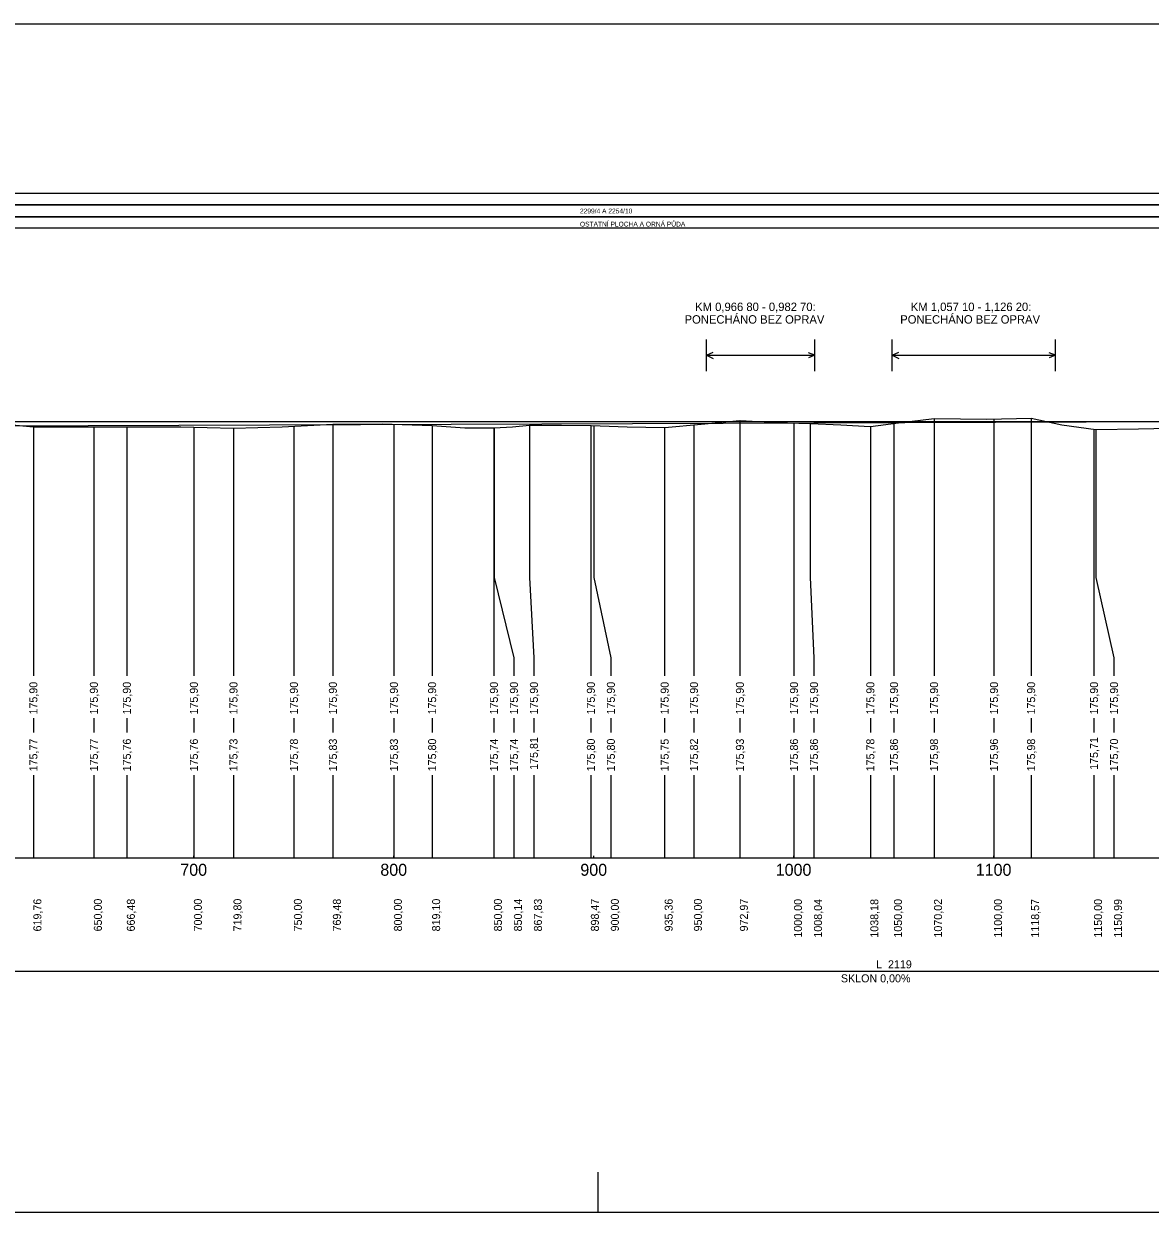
# Model space of a CAD drawing. Extents: x -614174 to -599765, y -1185887 to -1181080.
# Drawn here: x -612900 to -612336, y -1183382 to -1182788 of the extents above; entities that cross this region are included whole.
import ezdxf

# ---------------------------------------------------------------- set-up
doc = ezdxf.new("R2010")
doc.units = 0
for name, color, linetype in [('11', 7, 'Continuous'), ('13', 7, 'Continuous'), ('56', 7, 'Continuous'), ('návrh', 7, 'Continuous')]:
    doc.layers.add(name, color=color, linetype=linetype)

msp = doc.modelspace()

# ---------------------------------------------------------------- linework, layer by layer
msp.add_line((-613514.51, -1182987.26), (-611402.58, -1182987.26))
for points in [[(-612919.57, -1182987.61), (-612894.76, -1182989.95), (-612894.75, -1182989.95), (-612872.01, -1182989.86), (-612848.19, -1182989.96), (-612848.02, -1182989.96), (-612820.99, -1182989.96), (-612794.74, -1182990.58), (-612794.71, -1182990.58), (-612770.43, -1182989.89), (-612745.02, -1182988.57), (-612744.86, -1182988.56), (-612720.42, -1182988.46), (-612695.43, -1182989.26), (-612695.41, -1182989.26), (-612679.04, -1182990.36), (-612664.36, -1182990.36), (-612664.31, -1182990.36), (-612655.26, -1182989.95), (-612646.68, -1182989.08), (-612646.61, -1182989.07), (-612630.72, -1182988.97), (-612616.04, -1182989.26), (-612615.86, -1182989.26), (-612597.94, -1182989.85), (-612579.15, -1182990.26), (-612579.03, -1182990.26), (-612560.84, -1182988.5), (-612541.53, -1182986.67), (-612541.4, -1182986.66), (-612523.45, -1182987.78), (-612506.47, -1182988.15), (-612506.29, -1182988.16), (-612491.08, -1182988.8), (-612476.37, -1182989.64), (-612476.32, -1182989.64), (-612462.3, -1182987.86), (-612444.48, -1182985.65), (-612444.38, -1182985.64), (-612418.08, -1182986.06), (-612395.94, -1182985.57), (-612395.88, -1182985.56), (-612380.62, -1182988.96), (-612363.52, -1182991.27), (-612363.4, -1182991.29), (-612342.33, -1182990.94), (-612319.32, -1182990.34)], [(-612444.48, -1182985.65), (-612444.48, -1183065.26), (-612444.48, -1183105.26), (-612444.48, -1183114.34)], [(-612414.51, -1182985.98), (-612414.51, -1183065.26), (-612414.51, -1183105.26), (-612414.51, -1183114.34)], [(-612395.94, -1182985.57), (-612395.94, -1183065.26), (-612395.94, -1183105.26), (-612395.94, -1183114.34)], [(-612894.75, -1182989.95), (-612894.75, -1183065.26), (-612894.75, -1183105.26), (-612894.75, -1183114.34)], [(-612864.51, -1182989.89), (-612864.51, -1183065.26), (-612864.51, -1183105.26), (-612864.51, -1183114.34)], [(-612848.02, -1182989.96), (-612848.02, -1183065.26), (-612848.02, -1183105.26), (-612848.02, -1183114.34)], [(-612814.51, -1182990.11), (-612814.51, -1183065.26), (-612814.51, -1183105.26), (-612814.51, -1183114.34)], [(-612794.71, -1182990.58), (-612794.71, -1183065.26), (-612794.71, -1183105.26), (-612794.71, -1183114.34)], [(-612764.51, -1182989.58), (-612764.51, -1183065.26), (-612764.51, -1183105.26), (-612764.51, -1183114.34)], [(-612745.02, -1182988.57), (-612745.02, -1183065.26), (-612745.02, -1183105.26), (-612745.02, -1183114.34)], [(-612714.51, -1182988.65), (-612714.51, -1183065.26), (-612714.51, -1183105.26), (-612714.51, -1183114.34)], [(-612695.41, -1182989.26), (-612695.41, -1183065.26), (-612695.41, -1183105.26), (-612695.41, -1183114.34)], [(-612664.51, -1182990.36), (-612664.51, -1183065.26), (-612664.51, -1183105.26), (-612664.51, -1183114.34)], [(-612664.36, -1182990.36), (-612664.36, -1183065.26), (-612654.51, -1183105.26), (-612654.51, -1183114.34)], [(-612646.68, -1182989.08), (-612646.68, -1183065.26), (-612644.51, -1183105.26), (-612644.51, -1183114.34)], [(-612616.04, -1182989.26), (-612616.04, -1183065.26), (-612616.04, -1183105.26), (-612616.04, -1183114.34)], [(-612614.51, -1182989.3), (-612614.51, -1183065.26), (-612606.04, -1183105.26), (-612606.04, -1183114.34)], [(-612579.15, -1182990.26), (-612579.15, -1183065.26), (-612579.15, -1183105.26), (-612579.15, -1183114.34)], [(-612564.51, -1182988.86), (-612564.51, -1183065.26), (-612564.51, -1183105.26), (-612564.51, -1183114.34)], [(-612541.53, -1182986.67), (-612541.53, -1183065.26), (-612541.53, -1183105.26), (-612541.53, -1183114.34)], [(-612514.51, -1182987.97), (-612514.51, -1183065.26), (-612514.51, -1183105.26), (-612514.51, -1183114.34)], [(-612506.47, -1182988.15), (-612506.47, -1183065.26), (-612504.51, -1183105.26), (-612504.51, -1183114.34)], [(-612476.32, -1182989.64), (-612476.32, -1183065.26), (-612476.32, -1183105.26), (-612476.32, -1183114.34)], [(-612464.51, -1182988.13), (-612464.51, -1183065.26), (-612464.51, -1183105.26), (-612464.51, -1183114.34)], [(-612364.51, -1182991.14), (-612364.51, -1183065.26), (-612364.51, -1183105.26), (-612364.51, -1183114.34)], [(-612363.52, -1182991.27), (-612363.52, -1183065.26), (-612354.51, -1183105.26), (-612354.51, -1183114.34)], [(-612894.75, -1183135.54), (-612894.75, -1183142.7)], [(-612864.51, -1183135.54), (-612864.51, -1183142.7)], [(-612848.02, -1183135.54), (-612848.02, -1183142.7)], [(-612814.51, -1183135.54), (-612814.51, -1183142.7)], [(-612794.71, -1183135.54), (-612794.71, -1183142.7)], [(-612764.51, -1183135.54), (-612764.51, -1183142.7)], [(-612745.02, -1183135.54), (-612745.02, -1183142.7)], [(-612714.51, -1183135.54), (-612714.51, -1183142.7)], [(-612695.41, -1183135.54), (-612695.41, -1183142.7)], [(-612664.51, -1183135.54), (-612664.51, -1183142.7)], [(-612654.51, -1183135.54), (-612654.51, -1183142.7)], [(-612644.51, -1183135.54), (-612644.51, -1183142.7)], [(-612616.04, -1183135.54), (-612616.04, -1183142.7)], [(-612606.04, -1183135.54), (-612606.04, -1183142.7)], [(-612579.15, -1183135.54), (-612579.15, -1183142.7)], [(-612564.51, -1183135.54), (-612564.51, -1183142.7)], [(-612541.53, -1183135.54), (-612541.53, -1183142.7)], [(-612514.51, -1183135.54), (-612514.51, -1183142.7)], [(-612504.51, -1183135.54), (-612504.51, -1183142.7)], [(-612476.32, -1183135.54), (-612476.32, -1183142.7)], [(-612464.51, -1183135.54), (-612464.51, -1183142.7)], [(-612444.48, -1183135.54), (-612444.48, -1183142.7)], [(-612414.51, -1183135.54), (-612414.51, -1183142.7)], [(-612395.94, -1183135.54), (-612395.94, -1183142.7)], [(-612364.51, -1183135.54), (-612364.51, -1183142.7)], [(-612354.51, -1183135.54), (-612354.51, -1183142.7)], [(-612894.75, -1183163.91), (-612894.75, -1183205.26)], [(-612864.51, -1183163.91), (-612864.51, -1183205.26)], [(-612848.02, -1183163.91), (-612848.02, -1183205.26)], [(-612814.51, -1183163.91), (-612814.51, -1183205.26)], [(-612794.71, -1183163.91), (-612794.71, -1183205.26)], [(-612764.51, -1183163.91), (-612764.51, -1183205.26)], [(-612745.02, -1183163.91), (-612745.02, -1183205.26)], [(-612714.51, -1183163.91), (-612714.51, -1183205.26)], [(-612695.41, -1183163.91), (-612695.41, -1183205.26)], [(-612664.51, -1183163.91), (-612664.51, -1183205.26)], [(-612654.51, -1183163.91), (-612654.51, -1183205.26)], [(-612644.51, -1183163.91), (-612644.51, -1183205.26)], [(-612616.04, -1183163.91), (-612616.04, -1183205.26)], [(-612606.04, -1183163.91), (-612606.04, -1183205.26)], [(-612579.15, -1183163.91), (-612579.15, -1183205.26)], [(-612564.51, -1183163.91), (-612564.51, -1183205.26)], [(-612541.53, -1183163.91), (-612541.53, -1183205.26)], [(-612514.51, -1183163.91), (-612514.51, -1183205.26)], [(-612504.51, -1183163.91), (-612504.51, -1183205.26)], [(-612476.32, -1183163.91), (-612476.32, -1183205.26)], [(-612464.51, -1183163.91), (-612464.51, -1183205.26)], [(-612444.48, -1183163.91), (-612444.48, -1183205.26)], [(-612414.51, -1183163.91), (-612414.51, -1183205.26)], [(-612395.94, -1183163.91), (-612395.94, -1183205.26)], [(-612364.51, -1183163.91), (-612364.51, -1183205.26)], [(-612354.51, -1183163.91), (-612354.51, -1183205.26)], [(-613514.51, -1183261.99), (-611395.59, -1183261.99)]]:
    msp.add_lwpolyline(points)
at = {"layer": '56'}
for p, q in [((-613514.51, -1183205.26), (-611314.51, -1183205.26)), ((-612814.51, -1183205.26), (-612814.51, -1183204.26)), ((-612714.51, -1183205.26), (-612714.51, -1183204.26)), ((-612614.51, -1183205.26), (-612614.51, -1183204.26)), ((-612514.51, -1183205.26), (-612514.51, -1183204.26)), ((-612414.51, -1183205.26), (-612414.51, -1183204.26))]:
    msp.add_line(p, q, dxfattribs=at)
at = {"layer": 'návrh'}
for p, q in [((-613657.4, -1182788.43), (-610932.51, -1182788.43)), ((-612558.25, -1182961.98), (-612558.25, -1182946.2)), ((-612503.99, -1182961.98), (-612503.99, -1182946.2)), ((-612465.47, -1182961.98), (-612465.47, -1182946.2)), ((-612383.78, -1182961.98), (-612383.78, -1182946.2)), ((-612558.25, -1182954.09), (-612554.89, -1182952.64)), ((-612558.25, -1182954.09), (-612554.85, -1182955.65)), ((-612558.25, -1182954.09), (-612503.99, -1182954.09)), ((-612503.99, -1182954.09), (-612507.17, -1182952.85)), ((-612503.99, -1182954.09), (-612507.17, -1182955.45)), ((-612465.47, -1182954.09), (-612462.11, -1182952.64)), ((-612465.47, -1182954.09), (-612462.07, -1182955.65)), ((-612465.47, -1182954.09), (-612383.78, -1182954.09)), ((-612383.78, -1182954.09), (-612386.96, -1182952.85)), ((-612383.78, -1182954.09), (-612386.96, -1182955.45)), ((-611394.51, -1182984.06), (-613514.51, -1182991.66)), ((-612612.51, -1183362.43), (-612612.51, -1183382.43)), ((-613452.51, -1183382.43), (-610932.51, -1183382.43))]:
    msp.add_line(p, q, dxfattribs=at)
for points in [[(-613514.51, -1182873.17), (-611398.36, -1182873.17), (-611398.36, -1182879), (-613514.51, -1182879)], [(-613514.51, -1182879), (-611398.36, -1182879), (-611398.36, -1182884.84), (-613514.51, -1182884.84)], [(-613514.51, -1182884.84), (-611398.36, -1182884.84), (-611398.36, -1182890.67), (-613514.51, -1182890.67)]]:
    msp.add_lwpolyline(points, close=True, dxfattribs=at)

# ---------------------------------------------------------------- texts
at = {"layer": '11'}
for s, rotation, p in [('175,90', 90, (-612892.75, -1183133.67)), ('175,90', 90, (-612862.51, -1183133.67)), ('175,90', 90, (-612846.02, -1183133.67)), ('175,90', 90, (-612812.51, -1183133.67)), ('175,90', 90, (-612792.71, -1183133.67)), ('175,90', 90, (-612762.51, -1183133.67)), ('175,90', 90, (-612743.02, -1183133.67)), ('175,90', 90, (-612712.51, -1183133.67)), ('175,90', 90, (-612693.41, -1183133.67)), ('175,90', 90, (-612662.51, -1183133.67)), ('175,90', 90, (-612652.51, -1183133.67)), ('175,90', 90, (-612642.51, -1183133.67)), ('175,90', 90, (-612614.04, -1183133.67)), ('175,90', 90, (-612604.04, -1183133.67)), ('175,90', 90, (-612577.15, -1183133.67)), ('175,90', 90, (-612562.51, -1183133.67)), ('175,90', 90, (-612539.53, -1183133.67)), ('175,90', 90, (-612512.51, -1183133.67)), ('175,90', 90, (-612502.51, -1183133.67)), ('175,90', 90, (-612474.32, -1183133.67)), ('175,90', 90, (-612462.51, -1183133.67)), ('175,90', 90, (-612442.48, -1183133.67)), ('175,90', 90, (-612412.51, -1183133.67)), ('175,90', 90, (-612393.94, -1183133.67)), ('175,90', 90, (-612362.51, -1183133.67)), ('175,90', 90, (-612352.51, -1183133.67)), ('175,77', 90, (-612892.75, -1183162.09)), ('175,77', 90, (-612862.51, -1183162.09)), ('175,76', 90, (-612846.02, -1183162.09)), ('175,76', 90, (-612812.51, -1183162.09)), ('175,73', 90, (-612792.71, -1183162.09)), ('175,78', 90, (-612762.51, -1183162.1)), ('175,83', 90, (-612743.02, -1183162.09)), ('175,83', 90, (-612712.51, -1183162.09)), ('175,80', 90, (-612693.41, -1183162.07)), ('175,74', 90, (-612662.51, -1183162.07)), ('175,74', 90, (-612652.51, -1183162.07)), ('175,81', 90, (-612642.51, -1183161.32)), ('175,80', 90, (-612614.04, -1183162.07)), ('175,80', 90, (-612604.04, -1183162.07)), ('175,75', 90, (-612577.15, -1183162.12)), ('175,82', 90, (-612562.51, -1183162.05)), ('175,93', 90, (-612539.53, -1183162.09)), ('175,86', 90, (-612512.51, -1183162.09)), ('175,86', 90, (-612502.51, -1183162.09)), ('175,78', 90, (-612474.32, -1183162.1)), ('175,86', 90, (-612462.51, -1183162.09)), ('175,98', 90, (-612442.48, -1183162.1)), ('175,96', 90, (-612412.51, -1183162.09)), ('175,98', 90, (-612393.94, -1183162.1)), ('175,71', 90, (-612362.51, -1183161.32)), ('175,70', 90, (-612352.51, -1183162.07)), ('619,76', 90, (-612890.75, -1183242.09)), ('650,00', 90, (-612860.51, -1183242.07)), ('666,48', 90, (-612844.02, -1183242.1)), ('700,00', 90, (-612810.51, -1183242.07)), ('719,80', 90, (-612790.71, -1183242.07)), ('750,00', 90, (-612760.51, -1183242.07)), ('769,48', 90, (-612741.02, -1183242.1)), ('800,00', 90, (-612710.51, -1183242.07)), ('819,10', 90, (-612691.41, -1183242.07)), ('850,00', 90, (-612660.51, -1183242.07)), ('850,14', 90, (-612650.51, -1183242.07)), ('867,83', 90, (-612640.51, -1183242.09)), ('898,47', 90, (-612612.04, -1183242.09)), ('900,00', 90, (-612602.04, -1183242.07)), ('935,36', 90, (-612575.15, -1183242.09)), ('950,00', 90, (-612560.51, -1183242.07)), ('972,97', 90, (-612537.53, -1183242.09)), ('1000,00', 90, (-612510.51, -1183245.18)), ('1008,04', 90, (-612500.51, -1183245.18)), ('1038,18', 90, (-612472.32, -1183245.2)), ('1050,00', 90, (-612460.51, -1183245.18)), ('1070,02', 90, (-612440.48, -1183245.15)), ('1100,00', 90, (-612410.51, -1183245.18)), ('1118,57', 90, (-612391.94, -1183245.2)), ('1150,00', 90, (-612360.51, -1183245.18)), ('1150,99', 90, (-612350.51, -1183245.2)), ('L  2119', 360, (-612473.44, -1183260.53)), ('SKLON 0,00%', 360, (-612491.04, -1183267.53))]:
    msp.add_text(s, height=4, rotation=rotation, dxfattribs=at).set_placement(p)
at = {"layer": '13'}
for s, height, p in [('2299/4 A 2254/10', 2.4, (-612621.5, -1182883.21)), ('OSTATNÍ PLOCHA A ORNÁ PŮDA', 2.4, (-612621.5, -1182889.76)), ('PONECHÁNO BEZ OPRAV', 4.2, (-612569.19, -1182938.3)), ('KM 0,966 80 - 0,982 70: ', 4.2, (-612563.9, -1182932)), ('PONECHÁNO BEZ OPRAV', 4.2, (-612461.38, -1182938.3)), ('KM 1,057 10 - 1,126 20: ', 4.2, (-612456.09, -1182932)), ('700', 6, (-612821.3, -1183214.26)), ('800', 6, (-612721.3, -1183214.26)), ('900', 6, (-612621.3, -1183214.26)), ('1000', 6, (-612523.63, -1183214.26)), ('1100', 6, (-612423.63, -1183214.26))]:
    msp.add_text(s, height=height, dxfattribs=at).set_placement(p)

doc.saveas('drawing.dxf')
